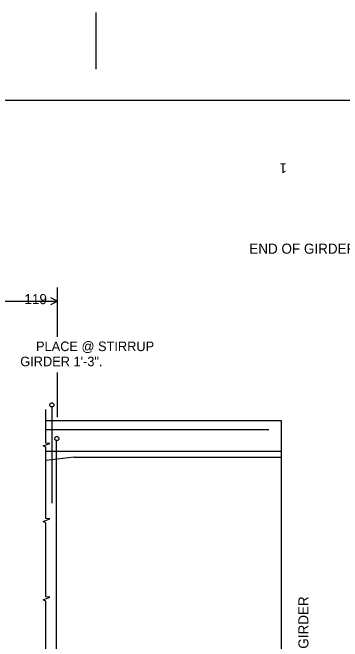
# Model space of a CAD drawing. Extents: x 1005.2 to 1101.8, y 1997.9 to 2073.7.
# Drawn here: x 1052.83 to 1063.75, y 2050.68 to 2071.46 of the extents above; entities that cross this region are included whole.
import ezdxf

# ---------------------------------------------------------------- set-up
doc = ezdxf.new("R2010")
doc.units = 0
for name, color, linetype in [('Level 1', 7, 'Continuous'), ('Level 2', 7, 'Continuous'), ('Level 37', 7, 'Continuous'), ('Level 60', 7, 'Continuous'), ('Level 7', 7, 'Continuous')]:
    doc.layers.add(name, color=color, linetype=linetype)

msp = doc.modelspace()

# ---------------------------------------------------------------- linework, layer by layer
at = {"layer": 'Level 1'}
msp.add_line((1097.4307555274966, 2068.5609856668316), (1013.7629986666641, 2068.5609856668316), dxfattribs=at)
at = {"layer": 'Level 2'}
for p, q in [((1054.323666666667, 2060.74825), (1054.323666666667, 2062.3755)), ((1025.35725, 2061.9230000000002), (1054.323666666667, 2061.9230000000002)), ((1054.323666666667, 2058.0925833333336), (1054.323666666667, 2059.5695833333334)), ((1053.929, 2057.231916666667), (1053.929, 2058.3388333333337)), ((1054.1347500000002, 2058.445416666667), (1054.1347500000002, 2055.249666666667)), ((1061.7311666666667, 2057.969416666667), (1053.929, 2057.969416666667)), ((1061.7311666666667, 2046.4125000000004), (1061.7311666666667, 2057.969416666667)), ((1061.3084166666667, 2057.6762500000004), (1053.929, 2057.6762500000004)), ((1053.8465, 2057.1375833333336), (1054.0706666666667, 2057.2200833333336)), ((1054.0706666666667, 2057.2200833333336), (1053.929, 2057.231916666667)), ((1054.2885, 2046.7277500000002), (1054.2885, 2057.314416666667)), ((1053.929, 2057.09425), (1053.8465, 2057.1375833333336)), ((1053.929, 2055.9922500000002), (1053.929, 2057.09425)), ((1053.929, 2056.96925), (1061.7331666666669, 2056.96925)), ((1054.8724166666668, 2056.7717500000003), (1053.929, 2056.657416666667)), ((1054.8724166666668, 2056.7717500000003), (1061.746, 2056.7717500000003)), ((1053.929, 2054.740166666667), (1053.929, 2056.4993333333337)), ((1053.8465, 2054.6458333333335), (1054.0706666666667, 2054.7283333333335)), ((1054.0706666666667, 2054.7283333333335), (1053.929, 2054.740166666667)), ((1053.929, 2054.6025000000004), (1053.8465, 2054.6458333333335)), ((1053.929, 2053.5005), (1053.929, 2054.6025000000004)), ((1053.929, 2052.1476666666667), (1053.929, 2053.9068333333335)), ((1053.8465, 2052.0533333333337), (1054.0706666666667, 2052.1358333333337)), ((1053.929, 2052.01), (1053.8465, 2052.0533333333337)), ((1054.0706666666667, 2052.1358333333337), (1053.929, 2052.1476666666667)), ((1053.929, 2050.9080000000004), (1053.929, 2052.01)), ((1053.929, 2049.6055833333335), (1053.929, 2051.36475))]:
    msp.add_line(p, q, dxfattribs=at)
msp.add_lwpolyline([(1054.0983333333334, 2061.809416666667), (1054.3205833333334, 2061.9205), (1054.0983333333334, 2062.0315833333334)], dxfattribs=at)
for centre in [(1054.1318333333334, 2058.496416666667), (1054.2978333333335, 2057.3825833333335)]:
    msp.add_circle(centre, 0.0693500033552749, dxfattribs=at)
at = {"layer": 'Level 37'}
msp.add_line((1055.5967659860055, 2069.5949854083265), (1055.5967659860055, 2071.4620960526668), dxfattribs=at)

# ---------------------------------------------------------------- texts
at = {"layer": 'Level 2'}
for s, p in [(' PLACE @ STIRRUP', (1053.4916666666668, 2060.2730833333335)), (' GIRDER 1\'-3".', (1052.9690833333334, 2059.772416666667))]:
    msp.add_text(s, height=0.31633350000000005, dxfattribs=at).set_placement(p)
msp.add_text('END OF GIRDER', height=0.33333350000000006, rotation=90, dxfattribs=at).set_placement((1062.623916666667, 2048.6292500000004))
at = {"layer": 'Level 60'}
msp.add_text('1', height=0.32343750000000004, rotation=180, dxfattribs=at).set_placement((1061.9080000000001, 2066.48075))
msp.add_text('119', height=0.33333350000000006, dxfattribs=at).set_placement((1053.2250000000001, 2061.82475))
at = {"layer": 'Level 7'}
msp.add_text('END OF GIRDERS', height=0.33333300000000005, dxfattribs=at).set_placement((1060.6665053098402, 2063.4922500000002))

doc.saveas('drawing.dxf')
